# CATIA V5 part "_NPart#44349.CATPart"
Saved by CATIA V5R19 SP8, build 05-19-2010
Part number: entretoise taraudée
Revision: ANY
Definition: UNKNOWN
Nomenclature: entretoise taraudée
Source: Unknown
Bounding box of the stored display mesh (mm): x 0 to 14, y -3 to 3, z -3 to 3
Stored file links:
  D:\Documents\1_Travail\1 - ac-limoges.fr\ac-limoges.fr\Emmanuel Maynard - STI2D_Turgot\2 -2I2D\2_SEQUENCE_Serrure_Biométrique\5-Spé_ITEC\Serrure_Bio_Eleve\_NPart#44349.CATPart
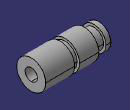
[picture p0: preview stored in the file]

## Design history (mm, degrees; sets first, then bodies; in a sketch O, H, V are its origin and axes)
Body1 "Enlèv. mat.-Extru.1" (main body)
  Solid1: solid without history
